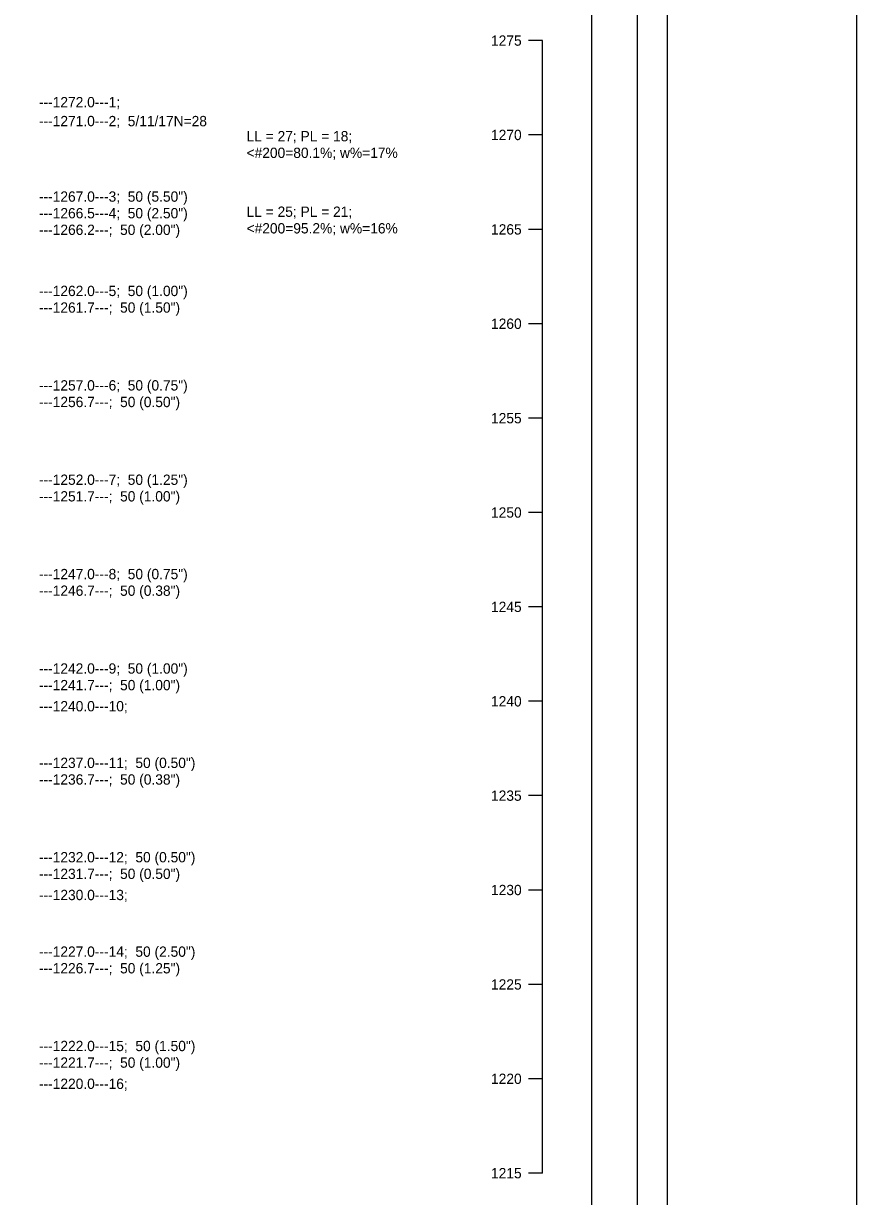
# Model space of a CAD drawing. Extents: x 2150161.5 to 2150203.1, y 143779.5 to 143868.5.
# Drawn here: x 2150193.04 to 2150203.07, y 143842.21 to 143856.33 of the extents above; entities that cross this region are included whole.
import ezdxf

# ---------------------------------------------------------------- set-up
doc = ezdxf.new("R2010")
doc.units = 0
for name, color, linetype in [('Default', 7, 'Continuous'), ('S', 7, 'Continuous'), ('SHT_Plot_Shape_Full', 7, 'Continuous'), ('SHT_Plot_Shape_Half', 7, 'Continuous'), ('SHT_Sheet_Border', 7, 'Continuous')]:
    doc.layers.add(name, color=color, linetype=linetype)

msp = doc.modelspace()

# ---------------------------------------------------------------- linework, layer by layer
at = {"layer": 'Default'}
msp.add_line((2150199.288, 143842.487), (2150199.288, 143856.123), dxfattribs=at)
for points in [[(2150199.288, 143856.123), (2150199.122, 143856.123)], [(2150199.288, 143854.987), (2150199.122, 143854.987)], [(2150199.288, 143853.85), (2150199.122, 143853.85)], [(2150199.288, 143852.714), (2150199.122, 143852.714)], [(2150199.288, 143851.577), (2150199.122, 143851.577)], [(2150199.288, 143850.441), (2150199.122, 143850.441)], [(2150199.288, 143849.305), (2150199.122, 143849.305)], [(2150199.288, 143848.168), (2150199.122, 143848.168)], [(2150199.288, 143847.032), (2150199.122, 143847.032)], [(2150199.288, 143845.896), (2150199.122, 143845.896)], [(2150199.288, 143844.759), (2150199.122, 143844.759)], [(2150199.288, 143843.623), (2150199.122, 143843.623)], [(2150199.288, 143842.487), (2150199.122, 143842.487)]]:
    msp.add_lwpolyline(points, dxfattribs=at)
at = {"layer": 'S'}
msp.add_lwpolyline([(2150161.53, 143868.477), (2150203.071, 143868.477), (2150203.071, 143779.536), (2150161.53, 143779.536)], close=True, dxfattribs=at)
at = {"layer": 'SHT_Plot_Shape_Full'}
msp.add_lwpolyline([(2150164.792, 143860.145), (2150200.792, 143860.145), (2150200.792, 143836.145), (2150164.792, 143836.145)], close=True, dxfattribs=at)
at = {"layer": 'SHT_Plot_Shape_Half'}
msp.add_lwpolyline([(2150166.429, 143859.32), (2150200.429, 143859.32), (2150200.429, 143837.32), (2150166.429, 143837.32)], close=True, dxfattribs=at)
at = {"layer": 'SHT_Sheet_Border'}
msp.add_lwpolyline([(2150199.879, 143837.82), (2150168.379, 143837.82), (2150168.379, 143858.82), (2150199.879, 143858.82)], close=True, dxfattribs=at)

# ---------------------------------------------------------------- texts
at = {"layer": 'Default'}
for s, p in [('1275', (2150198.669, 143856.061)), ('---1272.0---1;', (2150193.225, 143855.32)), ('---1271.0---2;  5/11/17N=28', (2150193.225, 143855.092)), ('LL = 27; PL = 18;', (2150195.725, 143854.91)), ('1270', (2150198.669, 143854.925)), ('<#200=80.1%; w%=17%', (2150195.725, 143854.71)), ('---1267.0---3;  50 (5.50")', (2150193.225, 143854.183)), ('---1266.5---4;  50 (2.50")', (2150193.225, 143853.983)), ('LL = 25; PL = 21;', (2150195.725, 143854.001)), ('<#200=95.2%; w%=16%', (2150195.725, 143853.801)), ('---1266.2---;  50 (2.00")', (2150193.225, 143853.783)), ('1265', (2150198.669, 143853.788)), ('---1262.0---5;  50 (1.00")', (2150193.225, 143853.047)), ('---1261.7---;  50 (1.50")', (2150193.225, 143852.847)), ('1260', (2150198.669, 143852.652)), ('---1257.0---6;  50 (0.75")', (2150193.225, 143851.91)), ('---1256.7---;  50 (0.50")', (2150193.225, 143851.71)), ('1255', (2150198.669, 143851.515)), ('---1252.0---7;  50 (1.25")', (2150193.225, 143850.774)), ('---1251.7---;  50 (1.00")', (2150193.225, 143850.574)), ('1250', (2150198.669, 143850.379)), ('---1247.0---8;  50 (0.75")', (2150193.225, 143849.638)), ('---1246.7---;  50 (0.38")', (2150193.225, 143849.438)), ('1245', (2150198.669, 143849.243)), ('---1242.0---9;  50 (1.00")', (2150193.225, 143848.501)), ('---1241.7---;  50 (1.00")', (2150193.225, 143848.301)), ('---1240.0---10;', (2150193.225, 143848.047)), ('1240', (2150198.669, 143848.106)), ('---1237.0---11;  50 (0.50")', (2150193.225, 143847.365)), ('---1236.7---;  50 (0.38")', (2150193.225, 143847.165)), ('1235', (2150198.669, 143846.97)), ('---1232.0---12;  50 (0.50")', (2150193.225, 143846.229)), ('---1231.7---;  50 (0.50")', (2150193.225, 143846.029)), ('---1230.0---13;', (2150193.225, 143845.774)), ('1230', (2150198.669, 143845.834)), ('---1227.0---14;  50 (2.50")', (2150193.225, 143845.092)), ('---1226.7---;  50 (1.25")', (2150193.225, 143844.892)), ('1225', (2150198.669, 143844.697)), ('---1222.0---15;  50 (1.50")', (2150193.225, 143843.956)), ('---1221.7---;  50 (1.00")', (2150193.225, 143843.756)), ('---1220.0---16;', (2150193.225, 143843.501)), ('1220', (2150198.669, 143843.561)), ('1215', (2150198.669, 143842.425))]:
    msp.add_text(s, height=0.124, dxfattribs=at).set_placement(p)

doc.saveas('drawing.dxf')
